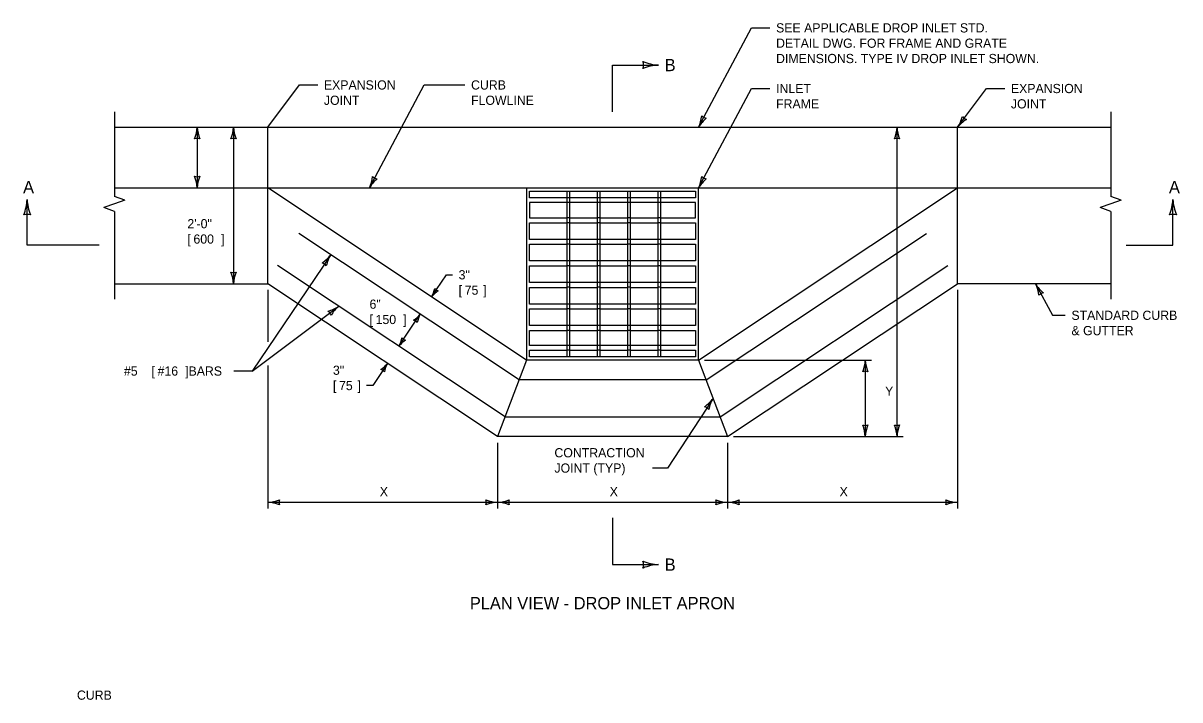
# Model space of a CAD drawing. Extents: x 49991.4 to 50048.3, y 49987.6 to 50018.3.
# Drawn here: x 50039.56 to 50047.11, y 50004.38 to 50008.79 of the extents above; entities that cross this region are included whole.
import ezdxf

# ---------------------------------------------------------------- set-up
doc = ezdxf.new("R2010")
doc.units = 0
for name, color, linetype in [('Level 1', 7, 'Continuous'), ('Level 2', 7, 'Continuous'), ('Level 3', 7, 'Continuous'), ('Level 4', 7, 'Continuous'), ('Level 6', 7, 'Continuous')]:
    doc.layers.add(name, color=color, linetype=linetype)

msp = doc.modelspace()

# ---------------------------------------------------------------- linework, layer by layer
at = {"layer": 'Level 1'}
for p, q in [((50040.1538, 50008.1123), (50046.6538, 50008.1123)), ((50041.1538, 50007.0909), (50041.1538, 50008.1123)), ((50045.6538, 50007.0909), (50045.6538, 50008.1123)), ((50040.1538, 50007.7165), (50046.6538, 50007.7165)), ((50042.8428, 50006.5936), (50041.1538, 50007.7165)), ((50042.8428, 50007.7159), (50042.8428, 50006.5936)), ((50043.9645, 50006.5936), (50045.6538, 50007.7165)), ((50043.9645, 50006.5936), (50043.9648, 50007.7159)), ((50042.8624, 50007.6962), (50043.9451, 50007.6962)), ((50042.8624, 50007.6519), (50042.8624, 50007.6962)), ((50043.1046, 50007.6519), (50042.8624, 50007.6519)), ((50043.1046, 50007.6962), (50043.1046, 50006.6135)), ((50043.1255, 50006.6135), (50043.1255, 50007.6962)), ((50043.3025, 50007.6519), (50043.1255, 50007.6519)), ((50043.3025, 50007.6962), (50043.3025, 50006.6135)), ((50043.3234, 50006.6135), (50043.3234, 50007.6962)), ((50043.5005, 50007.6519), (50043.3234, 50007.6519)), ((50043.5005, 50007.6962), (50043.5005, 50006.6135)), ((50043.5213, 50006.6135), (50043.5213, 50007.6962)), ((50043.6984, 50007.6519), (50043.5213, 50007.6519)), ((50043.6984, 50007.6962), (50043.6984, 50006.6135)), ((50043.7192, 50006.6135), (50043.7192, 50007.6962)), ((50043.9451, 50007.6519), (50043.7192, 50007.6519)), ((50043.9451, 50007.6962), (50043.9451, 50007.6519)), ((50042.8624, 50007.6207), (50042.8624, 50007.5211)), ((50043.1046, 50007.6207), (50042.8624, 50007.6207)), ((50043.3025, 50007.6207), (50043.1255, 50007.6207)), ((50043.5005, 50007.6207), (50043.3234, 50007.6207)), ((50043.6984, 50007.6207), (50043.5213, 50007.6207)), ((50043.9451, 50007.6207), (50043.7192, 50007.6207)), ((50043.9451, 50007.5211), (50043.9451, 50007.6207)), ((50042.8624, 50007.5211), (50043.1046, 50007.5211)), ((50042.8624, 50007.4899), (50043.1046, 50007.4899)), ((50042.8624, 50007.3805), (50042.8624, 50007.4899)), ((50043.1255, 50007.5211), (50043.3025, 50007.5211)), ((50043.1255, 50007.4899), (50043.3025, 50007.4899)), ((50043.3234, 50007.5211), (50043.5005, 50007.5211)), ((50043.3234, 50007.4899), (50043.5005, 50007.4899)), ((50043.5213, 50007.5211), (50043.6984, 50007.5211)), ((50043.5213, 50007.4899), (50043.6984, 50007.4899)), ((50043.7192, 50007.5211), (50043.9451, 50007.5211)), ((50043.7192, 50007.4899), (50043.9451, 50007.4899)), ((50043.9451, 50007.4899), (50043.9451, 50007.3805)), ((50043.1046, 50007.3805), (50042.8624, 50007.3805)), ((50042.8624, 50007.3492), (50043.1046, 50007.3492)), ((50042.8624, 50007.2399), (50042.8624, 50007.3492)), ((50043.3025, 50007.3805), (50043.1255, 50007.3805)), ((50043.1255, 50007.3492), (50043.3025, 50007.3492)), ((50043.5005, 50007.3805), (50043.3234, 50007.3805)), ((50043.3234, 50007.3492), (50043.5005, 50007.3492)), ((50043.6984, 50007.3805), (50043.5213, 50007.3805)), ((50043.5213, 50007.3492), (50043.6984, 50007.3492)), ((50043.9451, 50007.3805), (50043.7192, 50007.3805)), ((50043.7192, 50007.3492), (50043.9451, 50007.3492)), ((50043.9451, 50007.3492), (50043.9451, 50007.2399)), ((50043.1046, 50007.2399), (50042.8624, 50007.2399)), ((50042.8624, 50007.2086), (50043.1046, 50007.2086)), ((50042.8624, 50007.0992), (50042.8624, 50007.2086)), ((50043.3025, 50007.2399), (50043.1255, 50007.2399)), ((50043.1255, 50007.2086), (50043.3025, 50007.2086)), ((50043.5005, 50007.2399), (50043.3234, 50007.2399)), ((50043.3234, 50007.2086), (50043.5005, 50007.2086)), ((50043.6984, 50007.2399), (50043.5213, 50007.2399)), ((50043.5213, 50007.2086), (50043.6984, 50007.2086)), ((50043.9451, 50007.2399), (50043.7192, 50007.2399)), ((50043.7192, 50007.2086), (50043.9451, 50007.2086)), ((50043.9451, 50007.2086), (50043.9451, 50007.0992)), ((50043.1046, 50007.0992), (50042.8624, 50007.0992)), ((50043.3025, 50007.0992), (50043.1255, 50007.0992)), ((50043.5005, 50007.0992), (50043.3234, 50007.0992)), ((50043.6984, 50007.0992), (50043.5213, 50007.0992)), ((50043.9451, 50007.0992), (50043.7192, 50007.0992)), ((50040.1538, 50007.0909), (50041.1538, 50007.0909)), ((50042.6538, 50006.0936), (50041.1538, 50007.0909)), ((50042.8624, 50007.068), (50043.1046, 50007.068)), ((50042.8624, 50006.9586), (50042.8624, 50007.068)), ((50043.1255, 50007.068), (50043.3025, 50007.068)), ((50043.3234, 50007.068), (50043.5005, 50007.068)), ((50043.5213, 50007.068), (50043.6984, 50007.068)), ((50043.7192, 50007.068), (50043.9451, 50007.068)), ((50043.9451, 50007.068), (50043.9451, 50006.9586)), ((50044.1538, 50006.0936), (50045.6538, 50007.0909)), ((50046.6538, 50007.0909), (50045.6538, 50007.0909)), ((50043.1046, 50006.9586), (50042.8624, 50006.9586)), ((50043.3025, 50006.9586), (50043.1255, 50006.9586)), ((50043.5005, 50006.9586), (50043.3234, 50006.9586)), ((50043.6984, 50006.9586), (50043.5213, 50006.9586)), ((50043.9451, 50006.9586), (50043.7192, 50006.9586)), ((50042.8624, 50006.9274), (50043.1046, 50006.9274)), ((50042.8624, 50006.818), (50042.8624, 50006.9274)), ((50043.1255, 50006.9274), (50043.3025, 50006.9274)), ((50043.3234, 50006.9274), (50043.5005, 50006.9274)), ((50043.5213, 50006.9274), (50043.6984, 50006.9274)), ((50043.7192, 50006.9274), (50043.9451, 50006.9274)), ((50043.9451, 50006.9274), (50043.9451, 50006.818)), ((50043.1046, 50006.818), (50042.8624, 50006.818)), ((50043.3025, 50006.818), (50043.1255, 50006.818)), ((50043.5005, 50006.818), (50043.3234, 50006.818)), ((50043.6984, 50006.818), (50043.5213, 50006.818)), ((50043.9451, 50006.818), (50043.7192, 50006.818)), ((50042.8624, 50006.7867), (50043.1046, 50006.7867)), ((50042.8624, 50006.689), (50042.8624, 50006.7867)), ((50043.1255, 50006.7867), (50043.3025, 50006.7867)), ((50043.3234, 50006.7867), (50043.5005, 50006.7867)), ((50043.5213, 50006.7867), (50043.6984, 50006.7867)), ((50043.7192, 50006.7867), (50043.9451, 50006.7867)), ((50043.9451, 50006.7867), (50043.9451, 50006.689)), ((50043.1046, 50006.689), (50042.8624, 50006.689)), ((50042.8624, 50006.6578), (50043.1046, 50006.6578)), ((50042.8624, 50006.6135), (50042.8624, 50006.6578)), ((50043.3025, 50006.689), (50043.1255, 50006.689)), ((50043.1255, 50006.6578), (50043.3025, 50006.6578)), ((50043.5005, 50006.689), (50043.3234, 50006.689)), ((50043.3234, 50006.6578), (50043.5005, 50006.6578)), ((50043.6984, 50006.689), (50043.5213, 50006.689)), ((50043.5213, 50006.6578), (50043.6984, 50006.6578)), ((50043.9451, 50006.689), (50043.7192, 50006.689)), ((50043.7192, 50006.6578), (50043.9451, 50006.6578)), ((50043.9451, 50006.6578), (50043.9451, 50006.6135)), ((50042.8428, 50006.5936), (50042.6538, 50006.0936)), ((50043.9645, 50006.5936), (50042.8428, 50006.5936)), ((50043.9451, 50006.6135), (50042.8624, 50006.6135)), ((50043.9645, 50006.5936), (50044.1538, 50006.0936)), ((50044.1538, 50006.0936), (50042.6538, 50006.0936))]:
    msp.add_line(p, q, dxfattribs=at)
at = {"layer": 'Level 3'}
for p, q in [((50043.9648, 50008.1123), (50044.3106, 50008.7612)), ((50044.3106, 50008.7612), (50044.4306, 50008.7612)), ((50041.1538, 50008.1123), (50041.3602, 50008.3887)), ((50041.3602, 50008.3887), (50041.4802, 50008.3887)), ((50041.8174, 50007.7165), (50042.1744, 50008.3887)), ((50042.1744, 50008.3887), (50042.4405, 50008.3887)), ((50043.9648, 50007.7165), (50044.3106, 50008.3654)), ((50044.3106, 50008.3654), (50044.4306, 50008.3654)), ((50045.6538, 50008.1123), (50045.8428, 50008.3654)), ((50045.8428, 50008.3654), (50045.9628, 50008.3654)), ((50040.6936, 50008.1123), (50040.6936, 50007.7165)), ((50040.9307, 50008.1123), (50040.9307, 50007.0909)), ((50045.2597, 50006.0936), (50045.2597, 50008.1123)), ((50041.5649, 50007.2811), (50041.0516, 50006.5218)), ((50042.2233, 50007.0054), (50042.3193, 50007.1498)), ((50042.3193, 50007.1498), (50042.3593, 50007.1498)), ((50041.1538, 50007.0509), (50041.1538, 50006.7129)), ((50045.6538, 50007.0509), (50045.6538, 50005.6249)), ((50046.1638, 50007.0909), (50046.2742, 50006.8856)), ((50041.0516, 50006.5218), (50041.6177, 50006.9446)), ((50042.0096, 50006.684), (50042.1486, 50006.893)), ((50046.2742, 50006.8856), (50046.3575, 50006.8856)), ((50041.9349, 50006.5716), (50041.8389, 50006.4272)), ((50044.0045, 50006.5936), (50045.0924, 50006.5936)), ((50045.0524, 50006.5936), (50045.0524, 50006.0936)), ((50041.0516, 50006.5218), (50040.9316, 50006.5218)), ((50041.1538, 50006.5581), (50041.1538, 50005.6249)), ((50041.8389, 50006.4272), (50041.7989, 50006.4272)), ((50044.0592, 50006.3435), (50043.7625, 50005.8886)), ((50042.6538, 50006.0536), (50042.6538, 50005.6249)), ((50044.1538, 50006.0536), (50044.1538, 50005.6249)), ((50044.1938, 50006.0936), (50045.2997, 50006.0936)), ((50043.7625, 50005.8886), (50043.6634, 50005.8886)), ((50045.6538, 50005.6649), (50041.1538, 50005.6649))]:
    msp.add_line(p, q, dxfattribs=at)
for centre, radius, start, end in [((50043.5328, 50008.5186), 0.073, 342.13882, 17.86118), ((50043.7191, 50008.8289), 0.3107, 247.92284, 267.17269), ((50043.716, 50008.2224), 0.2964, 92.36048, 112.54399), ((50043.754, 50008.2116), 0.233, 334.77162, 354.02147), ((50044.1565, 50007.9997), 0.2223, 129.40032, 149.58383), ((50044.0251, 50008.2254), 0.0548, 224.08313, 259.80549), ((50045.4605, 50008.2423), 0.233, 326.07277, 345.32262), ((50045.8263, 50007.972), 0.2223, 120.70147, 140.88497), ((50045.7305, 50008.215), 0.0548, 215.38427, 251.10663), ((50040.4715, 50008.1215), 0.2223, 337.45601, 357.63952), ((50040.9264, 50008.1238), 0.233, 182.82731, 202.07716), ((50040.7086, 50008.1215), 0.2223, 337.45601, 357.63952), ((50041.1634, 50008.1238), 0.233, 182.82731, 202.07716), ((50045.0375, 50008.1215), 0.2223, 337.45601, 357.63952), ((50045.4924, 50008.1238), 0.233, 182.82731, 202.07716), ((50040.6936, 50007.9841), 0.0548, 72.13882, 107.86118), ((50040.9307, 50007.9841), 0.0548, 72.13882, 107.86118), ((50045.2597, 50007.9841), 0.0548, 72.13882, 107.86118), ((50040.6936, 50007.8447), 0.0548, 252.13882, 287.86118), ((50040.4609, 50007.705), 0.233, 2.82731, 22.07716), ((50040.9158, 50007.7073), 0.2223, 157.45601, 177.63952), ((50041.6065, 50007.8155), 0.233, 334.85439, 354.10424), ((50041.8776, 50007.8297), 0.0548, 224.1659, 259.88826), ((50043.754, 50007.8158), 0.233, 334.77162, 354.02147), ((50044.0251, 50007.8296), 0.0548, 224.08313, 259.80549), ((50042.0093, 50007.6042), 0.2223, 129.48309, 149.6666), ((50044.1565, 50007.6039), 0.2223, 129.40032, 149.58383), ((50039.2736, 50007.6575), 0.3107, 337.92284, 357.17269), ((50039.8801, 50007.6544), 0.2964, 182.36048, 202.54399), ((50046.7639, 50007.6544), 0.2964, 337.45601, 357.63952), ((50047.3704, 50007.6575), 0.3107, 182.82731, 202.07716), ((50039.5839, 50007.4712), 0.073, 72.13882, 107.86118), ((50047.0601, 50007.4712), 0.073, 72.13882, 107.86118), ((50041.3859, 50007.413), 0.2223, 303.39863, 323.58214), ((50041.7641, 50007.1603), 0.233, 148.76993, 168.01978), ((50041.493, 50007.1748), 0.0548, 38.08144, 73.8038), ((50040.9307, 50007.2191), 0.0548, 252.13882, 287.86118), ((50040.698, 50007.0794), 0.233, 2.82731, 22.07716), ((50041.1528, 50007.0817), 0.2223, 157.45601, 177.63952), ((50042.0627, 50007.0938), 0.1833, 331.1805, 349.66587), ((50042.0627, 50007.0938), 0.1833, 331.1805, 349.66587), ((50042.3596, 50006.8996), 0.1725, 122.5156, 142.16919), ((50042.3596, 50006.8996), 0.1725, 122.5156, 142.16919), ((50042.279, 50007.0892), 0.0458, 218.20225, 254.56331), ((50042.279, 50007.0892), 0.0458, 218.20225, 254.56331), ((50045.9638, 50006.9937), 0.2223, 5.73009, 25.9136), ((50046.3633, 50007.2112), 0.233, 211.10139, 230.35124), ((50046.2245, 50006.978), 0.0548, 100.4129, 136.13526), ((50041.4921, 50007.128), 0.2223, 284.21188, 304.39538), ((50041.5149, 50006.8679), 0.0548, 18.89468, 54.61705), ((50041.7661, 50006.765), 0.233, 129.58318, 148.83303), ((50042.0123, 50006.9988), 0.1725, 302.5156, 322.16919), ((50042.0123, 50006.9988), 0.1725, 302.5156, 322.16919), ((50042.3092, 50006.8046), 0.1833, 151.1805, 169.66587), ((50042.3092, 50006.8046), 0.1833, 151.1805, 169.66587), ((50042.0928, 50006.8092), 0.0458, 38.20225, 74.56331), ((50042.0928, 50006.8092), 0.0458, 38.20225, 74.56331), ((50041.849, 50006.7724), 0.1833, 331.1805, 349.66587), ((50041.849, 50006.7724), 0.1833, 331.1805, 349.66587), ((50042.1459, 50006.5782), 0.1725, 122.5156, 142.16919), ((50042.1459, 50006.5782), 0.1725, 122.5156, 142.16919), ((50042.0653, 50006.7678), 0.0458, 218.20225, 254.56331), ((50042.0653, 50006.7678), 0.0458, 218.20225, 254.56331), ((50041.7986, 50006.6774), 0.1725, 302.5156, 322.16919), ((50041.7986, 50006.6774), 0.1725, 302.5156, 322.16919), ((50042.0955, 50006.4832), 0.1833, 151.1805, 169.66587), ((50042.0955, 50006.4832), 0.1833, 151.1805, 169.66587), ((50044.8303, 50006.6028), 0.2223, 337.45601, 357.63952), ((50045.2851, 50006.6051), 0.233, 182.82731, 202.07716), ((50041.8792, 50006.4878), 0.0458, 38.20225, 74.56331), ((50041.8792, 50006.4878), 0.0458, 38.20225, 74.56331), ((50045.0524, 50006.4654), 0.0548, 72.13882, 107.86118), ((50043.8783, 50006.4728), 0.2223, 304.27723, 324.46074), ((50044.2602, 50006.2258), 0.233, 149.64853, 168.89838), ((50043.989, 50006.2362), 0.0548, 38.96004, 74.6824), ((50045.0524, 50006.2218), 0.0548, 252.13882, 287.86118), ((50044.8197, 50006.0821), 0.233, 2.82731, 22.07716), ((50045.2746, 50006.0845), 0.2223, 157.45601, 177.63952), ((50045.2597, 50006.2218), 0.0548, 252.13882, 287.86118), ((50045.027, 50006.0821), 0.233, 2.82731, 22.07716), ((50045.4818, 50006.0845), 0.2223, 157.45601, 177.63952), ((50041.1423, 50005.8976), 0.233, 272.82731, 292.07716), ((50041.1446, 50005.4428), 0.2223, 67.45601, 87.63952), ((50041.282, 50005.6649), 0.0548, 162.13882, 197.86118), ((50042.5256, 50005.6649), 0.0548, 342.13882, 17.86118), ((50042.6653, 50005.8976), 0.233, 247.92284, 267.17269), ((50042.6629, 50005.4428), 0.2223, 92.36048, 112.54399), ((50042.6423, 50005.8976), 0.233, 272.82731, 292.07716), ((50042.6446, 50005.4428), 0.2223, 67.45601, 87.63952), ((50042.782, 50005.6649), 0.0548, 162.13882, 197.86118), ((50044.0256, 50005.6649), 0.0548, 342.13882, 17.86118), ((50044.1653, 50005.8976), 0.233, 247.92284, 267.17269), ((50044.1629, 50005.4428), 0.2223, 92.36048, 112.54399), ((50044.1423, 50005.8976), 0.233, 272.82731, 292.07716), ((50044.1446, 50005.4428), 0.2223, 67.45601, 87.63952), ((50044.282, 50005.6649), 0.0548, 162.13882, 197.86118), ((50045.5256, 50005.6649), 0.0548, 342.13882, 17.86118), ((50045.6653, 50005.8976), 0.233, 247.92284, 267.17269), ((50045.6629, 50005.4428), 0.2223, 92.36048, 112.54399), ((50043.716, 50005.5548), 0.2964, 247.45601, 267.63952), ((50043.5328, 50005.2586), 0.073, 342.13882, 17.86118), ((50043.7191, 50004.9484), 0.3107, 92.82731, 112.07716)]:
    msp.add_arc(centre, radius, start, end, dxfattribs=at)
at = {"layer": 'Level 4'}
for p, q in [((50043.1255, 50007.6519), (50043.1046, 50007.6519)), ((50043.3234, 50007.6519), (50043.3025, 50007.6519)), ((50043.5213, 50007.6519), (50043.5005, 50007.6519)), ((50043.7192, 50007.6519), (50043.6984, 50007.6519)), ((50043.1255, 50007.6207), (50043.1046, 50007.6207)), ((50043.3234, 50007.6207), (50043.3025, 50007.6207)), ((50043.5213, 50007.6207), (50043.5005, 50007.6207)), ((50043.7192, 50007.6207), (50043.6984, 50007.6207)), ((50043.1255, 50007.5211), (50043.1046, 50007.5211)), ((50043.1255, 50007.4899), (50043.1046, 50007.4899)), ((50043.3234, 50007.5211), (50043.3025, 50007.5211)), ((50043.3234, 50007.4899), (50043.3025, 50007.4899)), ((50043.5213, 50007.5211), (50043.5005, 50007.5211)), ((50043.5213, 50007.4899), (50043.5005, 50007.4899)), ((50043.7192, 50007.5211), (50043.6984, 50007.5211)), ((50043.7192, 50007.4899), (50043.6984, 50007.4899)), ((50042.7938, 50006.4641), (50041.3561, 50007.4199)), ((50044.0135, 50006.4641), (50045.4515, 50007.4199)), ((50043.1255, 50007.3805), (50043.1046, 50007.3805)), ((50043.1255, 50007.3493), (50043.1046, 50007.3493)), ((50043.3234, 50007.3805), (50043.3025, 50007.3805)), ((50043.3234, 50007.3493), (50043.3025, 50007.3493)), ((50043.5213, 50007.3805), (50043.5005, 50007.3805)), ((50043.5213, 50007.3493), (50043.5005, 50007.3493)), ((50043.7192, 50007.3805), (50043.6984, 50007.3805)), ((50043.7192, 50007.3493), (50043.6984, 50007.3493)), ((50042.7028, 50006.2232), (50041.2171, 50007.2109)), ((50043.1255, 50007.2399), (50043.1046, 50007.2399)), ((50043.1255, 50007.2087), (50043.1046, 50007.2087)), ((50043.3234, 50007.2399), (50043.3025, 50007.2399)), ((50043.3234, 50007.2087), (50043.3025, 50007.2087)), ((50043.5213, 50007.2399), (50043.5005, 50007.2399)), ((50043.5213, 50007.2087), (50043.5005, 50007.2087)), ((50043.7192, 50007.2399), (50043.6984, 50007.2399)), ((50043.7192, 50007.2087), (50043.6984, 50007.2087)), ((50044.1047, 50006.2232), (50045.5904, 50007.2109)), ((50043.1255, 50007.0992), (50043.1046, 50007.0992)), ((50043.3234, 50007.0992), (50043.3025, 50007.0992)), ((50043.5213, 50007.0992), (50043.5005, 50007.0992)), ((50043.7192, 50007.0992), (50043.6984, 50007.0992)), ((50043.1255, 50007.0681), (50043.1046, 50007.0681)), ((50043.3234, 50007.0681), (50043.3025, 50007.0681)), ((50043.5213, 50007.0681), (50043.5005, 50007.0681)), ((50043.7192, 50007.0681), (50043.6984, 50007.0681)), ((50043.1255, 50006.9586), (50043.1046, 50006.9586)), ((50043.3234, 50006.9586), (50043.3025, 50006.9586)), ((50043.5213, 50006.9586), (50043.5005, 50006.9586)), ((50043.7192, 50006.9586), (50043.6984, 50006.9586)), ((50043.1255, 50006.9274), (50043.1046, 50006.9274)), ((50043.3234, 50006.9274), (50043.3025, 50006.9274)), ((50043.5213, 50006.9274), (50043.5005, 50006.9274)), ((50043.7192, 50006.9274), (50043.6984, 50006.9274)), ((50043.1255, 50006.818), (50043.1046, 50006.818)), ((50043.3234, 50006.818), (50043.3025, 50006.818)), ((50043.5213, 50006.818), (50043.5005, 50006.818)), ((50043.7192, 50006.818), (50043.6984, 50006.818)), ((50043.1255, 50006.7868), (50043.1046, 50006.7868)), ((50043.3234, 50006.7868), (50043.3025, 50006.7868)), ((50043.5213, 50006.7868), (50043.5005, 50006.7868)), ((50043.7192, 50006.7868), (50043.6984, 50006.7868)), ((50043.1255, 50006.689), (50043.1046, 50006.689)), ((50043.1255, 50006.6578), (50043.1046, 50006.6578)), ((50043.3234, 50006.689), (50043.3025, 50006.689)), ((50043.3234, 50006.6578), (50043.3025, 50006.6578)), ((50043.5213, 50006.689), (50043.5005, 50006.689)), ((50043.5213, 50006.6578), (50043.5005, 50006.6578)), ((50043.7192, 50006.689), (50043.6984, 50006.689)), ((50043.7192, 50006.6578), (50043.6984, 50006.6578)), ((50044.0135, 50006.4641), (50042.7938, 50006.4641)), ((50042.7028, 50006.2232), (50044.1047, 50006.2232))]:
    msp.add_line(p, q, dxfattribs=at)
at = {"layer": 'Level 6'}
for p, q in [((50043.4038, 50008.2123), (50043.4038, 50008.5186)), ((50043.4038, 50008.5186), (50043.7038, 50008.5186)), ((50040.1538, 50008.2123), (50040.1538, 50007.6609)), ((50046.6538, 50008.2123), (50046.6538, 50007.6609)), ((50039.5839, 50007.3422), (50039.5839, 50007.6422)), ((50040.2224, 50007.6366), (50040.1538, 50007.6609)), ((50040.2224, 50007.6366), (50040.1538, 50007.6123)), ((50046.7224, 50007.6366), (50046.6538, 50007.6609)), ((50046.7224, 50007.6366), (50046.6538, 50007.6123)), ((50047.0601, 50007.3422), (50047.0601, 50007.6422)), ((50040.1538, 50007.6123), (50040.0852, 50007.588)), ((50040.1538, 50007.5637), (50040.0852, 50007.588)), ((50040.1538, 50007.5637), (50040.1538, 50006.9909)), ((50046.6538, 50007.6123), (50046.5852, 50007.588)), ((50046.6538, 50007.5637), (50046.5852, 50007.588)), ((50046.6538, 50007.5637), (50046.6538, 50006.9909)), ((50040.0538, 50007.3422), (50039.5839, 50007.3422)), ((50046.7538, 50007.3422), (50047.0601, 50007.3422)), ((50043.4038, 50005.5649), (50043.4038, 50005.2586)), ((50043.4038, 50005.2586), (50043.7038, 50005.2586))]:
    msp.add_line(p, q, dxfattribs=at)

# ---------------------------------------------------------------- texts
at = {"layer": 'Level 2'}
for s, height, p in [('SEE APPLICABLE DROP INLET STD.', 0.06, (50044.4706, 50008.7312)), ('DETAIL DWG. FOR FRAME AND GRATE', 0.06, (50044.4706, 50008.6312)), ('B', 0.08, (50043.7438, 50008.4786)), ('DIMENSIONS. TYPE IV DROP INLET SHOWN.', 0.06, (50044.4706, 50008.5312)), ('EXPANSION', 0.06, (50041.5202, 50008.3587)), ('CURB', 0.06, (50042.4805, 50008.3587)), ('INLET', 0.06, (50044.4706, 50008.3354)), ('EXPANSION', 0.06, (50046.0028, 50008.3354)), ('JOINT', 0.06, (50041.5202, 50008.2587)), ('FLOWLINE', 0.06, (50042.4805, 50008.2587)), ('FRAME', 0.06, (50044.4706, 50008.2354)), ('JOINT', 0.06, (50046.0028, 50008.2354)), ('A', 0.08, (50039.5577, 50007.6822)), ('A', 0.08, (50047.0339, 50007.6822)), ('2\'-0"', 0.06, (50040.6294, 50007.4533)), ('[', 0.06, (50040.6294, 50007.3533)), ('600', 0.06, (50040.6691, 50007.3533)), (']', 0.06, (50040.8491, 50007.3533)), ('3"', 0.06, (50042.3993, 50007.1198)), ('[', 0.06, (50042.3993, 50007.0198)), ('75', 0.06, (50042.439, 50007.0198)), (']', 0.06, (50042.559, 50007.0198)), ('6"', 0.06, (50041.818, 50006.9283)), ('[', 0.06, (50041.818, 50006.8283)), ('150', 0.06, (50041.8577, 50006.8283)), (']', 0.06, (50042.0377, 50006.8283)), ('STANDARD CURB', 0.06, (50046.3975, 50006.8556)), ('& GUTTER', 0.06, (50046.3975, 50006.7556)), ('#5 ', 0.06, (50040.2156, 50006.4918)), ('[', 0.06, (50040.3956, 50006.4918)), ('#16', 0.06, (50040.4352, 50006.4918)), (']', 0.06, (50040.6152, 50006.4918)), (' BARS', 0.06, (50040.6148, 50006.4918)), ('3"', 0.06, (50041.5793, 50006.4972)), ('[', 0.06, (50041.5793, 50006.3972)), ('75', 0.06, (50041.619, 50006.3972)), (']', 0.06, (50041.739, 50006.3972)), ('Y', 0.06, (50045.1819, 50006.3609)), ('CONTRACTION', 0.06, (50043.0244, 50005.9586)), ('JOINT (TYP)', 0.06, (50043.0244, 50005.8586)), ('X', 0.06, (50041.8849, 50005.7049)), ('X', 0.06, (50043.3849, 50005.7049)), ('X', 0.06, (50044.8849, 50005.7049)), ('B', 0.08, (50043.7438, 50005.2186)), ('PLAN VIEW - DROP INLET APRON', 0.08, (50042.4726, 50004.9671)), ('CURB', 0.06, (50039.909, 50004.3769))]:
    msp.add_text(s, height=height, dxfattribs=at).set_placement(p)

doc.saveas('drawing.dxf')
